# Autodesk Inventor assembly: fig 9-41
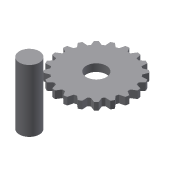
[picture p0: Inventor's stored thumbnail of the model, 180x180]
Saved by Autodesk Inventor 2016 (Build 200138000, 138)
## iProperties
Created: 2013-07
Part Number: fig 9-41
Document SubType Name: Assembly
Designer: CADCIM
Author: CADCIM
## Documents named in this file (3)
- D:\KAVITA\Autodesk Inventor_ 2016 Project_Kavita\Inventor_Part Files\Inventor_2016_Part\c09_Inv_2016\c09_inv_2016_prt\fig 9-41.iam
- D:\KAVITA\Autodesk Inventor_ 2016 Project_Kavita\Inventor_Part Files\Inventor_2016_Part\c09_Inv_2016\c09_inv_2016_prt\13.ipt
- D:\KAVITA\Autodesk Inventor_ 2016 Project_Kavita\Inventor_Part Files\Inventor_2016_Part\c09_Inv_2016\c09_inv_2016_prt\14.ipt
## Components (2 placed, 2 different names)
1. 13:1
2. 14:1
